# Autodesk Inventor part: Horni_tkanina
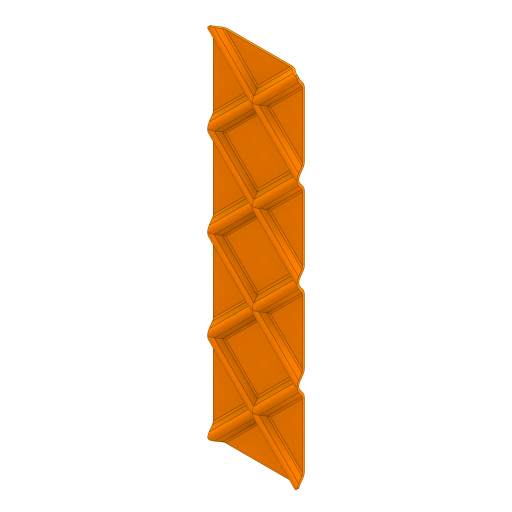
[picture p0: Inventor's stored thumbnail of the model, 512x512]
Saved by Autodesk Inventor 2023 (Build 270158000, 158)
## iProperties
Created: 2025-03
Part Number: Horni_tkanina
Material: Všeobecné
Document SubType Name: Modeling
Designer: tomik
Density: 1 g/cm^3
Appearance: Výchozí(1)
Author: tomik
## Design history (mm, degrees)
sketch "Náčrt1"
  geometry: L1 (0, 0)-(211.67, 0); L2 (0, 0)-(200, 200)
  constraints: 4 end point, 1 horizontal
  dimensions: "d1" = 45 deg angle of L1 L2; "d2" = 200 distance from line of L2.end L1
node "Pracovní rovina2"
sketch "Náčrt2"
  geometry: L1 (0, 0)-(0, 13.004); L2 (0, 0)-(-15.85, 0); L3 (0, 0)-(-4, 0); L4 (-3.268, 0.732)-(0, 4); L5 (0, 0)-(15.85, 0); L6 (0, 0)-(4, 0); L7 (3.268, 0.732)-(0, 4); L8 (0, 0)-(15.85, 0); L9 (5.036, 0)-(-5.036, 0); A1 r 2.5 centre (-5.036, 2.5) between (-5.036, 0) and (-3.268, 0.732); A2 r 2.5 centre (5.036, 2.5) between (3.268, 0.732) and (5.036, 0); 2 further points
  constraints: 18 end point, 5 point on line, 5 symmetric about line, 4 point on circle, 4 tangent, 2 centre point, 1 collinear, 1 horizontal, 1 vertical, 1 other
  dimensions: "d3" = 4 distance of L1.start L3.end; "d4" = 4 distance of L4.end L1.start; "d5" = 5 diameter of A1; "d6" = 5.03553 distance from line of L9.end L1
extrude "Vysunutí1" new body sketch "Náčrt2" distance "d7" = 200; taper "d8" = 0 deg
node "Pracovní rovina6"
fillet "Zaoblení3" dims "d14" = 2
mirror "Zrcadlit3"
node "Pracovní rovina10"
  node "Pracovní rovina9"
node "Pracovní rovina11"
pattern_linear "Obdélníkové pole1"
sketch "Náčrt3"
  geometry: 1 further point
sketch "Náčrt4"
  geometry: L1 (-30.32, -10.071)-(-30.32, 0) reference; L2 (-30.32, 0)-(0, 0) reference; L3 (10.071, -40.391)-(10.071, -10.071) reference; L4 (0, -40.391)-(10.071, -40.391) reference; L5 (-30.32, -3.621)-(-30.32, -6.45) reference; L6 (-30.32, -5.036)-(5.036, -40.391); L7 (-30.32, -5.036)-(111.102, 136.386); L8 (111.102, 136.386)-(146.457, 101.03); L9 (146.457, 101.03)-(5.036, -40.391); L10 (40.391, 415.738)-(-248.096, 101.03); L11 (-248.096, 101.03)-(128.779, -294.975); L12 (128.779, -294.975)-(406.838, 40.162); L13 (406.838, 40.162)-(40.391, 415.738); 7 further points
  constraints: 16 end point, 2 perpendicular, 1 coincident, 1 midpoint
  dimensions: "d23" = 200 distance of L6.start L7.end; "d24" = 50 distance of L7.end L8.end
extrude "Vysunutí2" cut sketch "Náčrt4" distance "d25" = 200; taper "d26" = 0 deg
fillet "Zaoblení5" dims "d27" = 1
fillet "Zaoblení6" dims "d28" = 1
feature "Odstranit plochu1"
feature "Zesílit1" dims "d29" = 1
sketch "Náčrt5"
  geometry: L1 (0, 56.121)-(0, 50) reference; L2 (7.121, 57.121)-(1, 57.121) reference; L3 (49, 57.121)-(42.879, 57.121) reference; L4 (50, 50)-(50, 56.121) reference; L5 (0, 14.243)-(0, 0) reference; L6 (0, -35.757)-(0, -50) reference; L7 (0, -85.757)-(0, -100) reference; L8 (0, -135.757)-(0, -141.879) reference; L9 (1, -142.879)-(7.121, -142.879) reference; L10 (42.879, -142.879)-(49, -142.879) reference; L11 (50, -141.879)-(50, -135.757) reference; L12 (50, -100)-(50, -85.757) reference; L13 (50, -50)-(50, -35.757) reference; L14 (50, 0)-(50, 14.243) reference; L15 (0, 11.743)-(0, 14.243) reference; L16 (0, 50)-(0, 14.243); L17 (25, 39.243)-(7.121, 57.121) reference; L18 (45.379, 57.121)-(42.879, 57.121) reference; L19 (7.121, 57.121)-(42.879, 57.121); L20 (50, 50)-(51, 51) reference; L21 (50, -135.757)-(51, -136.757) reference; L22 (50, 50)-(50, -135.757); L23 (4.621, -142.879)-(7.121, -142.879) reference; L24 (7.121, -142.879)-(42.879, -142.879); L25 (-27.274, 75.119)-(-18.089, -162.081); L26 (-18.089, -162.081)-(84.5, -170.257); L27 (84.5, -170.257)-(94.864, 79.849); L28 (94.864, 79.849)-(-27.274, 75.119); L29 (0, 0)-(-1, 1) reference; L30 (0, -135.757)-(-1, -136.757) reference; L31 (0, 0)-(0, -135.757); A1 r 1 centre (1, 56.121) between (1, 57.121) and (0, 56.121) reference; A2 r 1 centre (49, 56.121) between (50, 56.121) and (49, 57.121) reference; A3 r 1 centre (1, -141.879) between (0, -141.879) and (1, -142.879) reference; A4 r 1 centre (49, -141.879) between (49, -142.879) and (50, -141.879) reference; 11 further points
  constraints: 18 end point, 2 collinear, 1 horizontal, 1 perpendicular
extrude "Vysunutí3" cut sketch "Náčrt5" distance "d30" = 10; taper "d31" = 0 deg
sketch "Náčrt6"
  geometry: L1 (-25.284, 0)-(0, 0) reference; L2 (-25.284, 1)-(0, 1) reference; L3 (-25.284, 0)-(-25.284, 1) reference; L4 (0, 0)-(0, 1) reference; 1 further point
extrude "Vysunutí4" join sketch "Náčrt6" stored distance "d32" = 10; taper "d33" = 0 deg
sketch "Náčrt8"
  geometry: L1 (-7.121, 1)-(-7.121, 0) reference; L2 (-42.879, 0)-(-42.879, 1) reference; L3 (-7.121, 0)-(-7.121, 1) reference; L4 (-42.879, 0)-(-25, 0) reference; L5 (-7.121, 0)-(-42.879, 0); L6 (-42.879, 1)-(-25, 1) reference; L7 (-42.879, 1)-(-7.121, 1); L8 (-17.879, 1)-(0, 1) reference; 3 further points
  constraints: 4 end point, 2 collinear
extrude "Vysunutí5" join sketch "Náčrt8" stored distance "d34" = 10; taper "d35" = 0 deg
sketch "Náčrt9"
  geometry: L1 (42.879, 1)-(42.879, 0) reference; L2 (7.121, 0)-(7.121, 1) reference; L3 (42.879, 1)-(7.121, 1); L4 (25, 0)-(42.879, 0) reference; L5 (42.879, 0)-(7.121, 0); 2 further points
  constraints: 4 end point, 1 collinear
extrude "Vysunutí6" join sketch "Náčrt9" stored distance "d36" = 10; taper "d37" = 0 deg
pattern_linear "Obdélníkové pole2" dims "d40" = 50
node "Pracovní rovina12"
node "Pracovní rovina13"
mirror "Zrcadlit4"
mirror "Zrcadlit5"
mirror "Zrcadlit6"
node "Pracovní rovina14"
mirror "Zrcadlit7"
node "Těleso1"
other parameters: "d11" = 25, "d18" = 25, "d41" = 25, "d43" = 25
